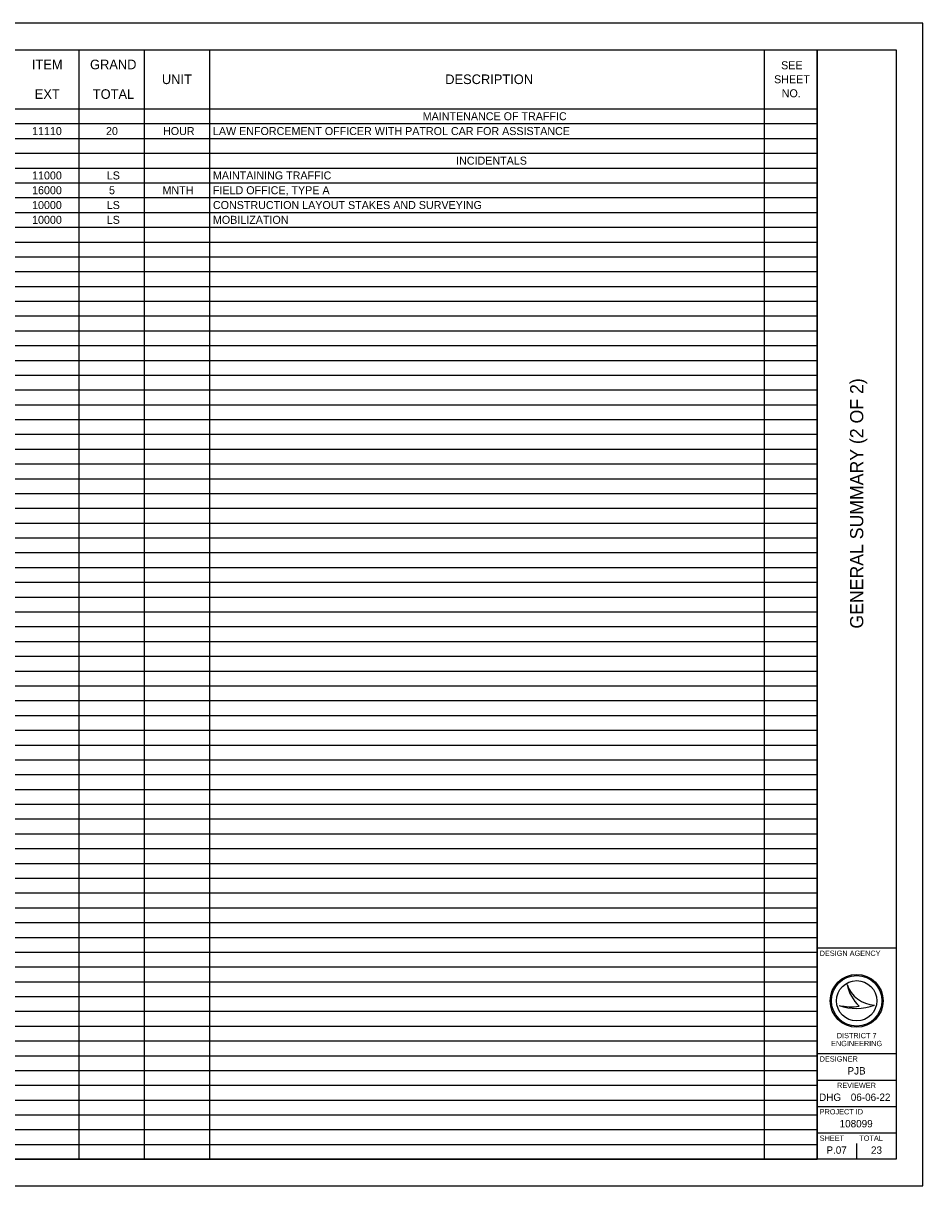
# Model space of a CAD drawing. Extents: x 0 to 34, y 0 to 22.
# Drawn here: x 16.98 to 34, y 0 to 22 of the extents above; entities that cross this region are included whole.
import ezdxf

# ---------------------------------------------------------------- set-up
doc = ezdxf.new("R2010")
doc.units = 0
for name, color, linetype in [('Default', 7, 'Continuous'), ('SH_Border', 7, 'Continuous'), ('SH_Cut_Line', 7, 'Continuous'), ('SH_Data', 7, 'Continuous'), ('SH_Text', 7, 'Continuous')]:
    doc.layers.add(name, color=color, linetype=linetype)

msp = doc.modelspace()

# ---------------------------------------------------------------- linework, layer by layer
at = {"layer": 'Default'}
for p, q in [((1.5, 21.5), (32.001, 21.5)), ((18.035, 21.5), (18.035, 0.502)), ((19.27, 21.5), (19.27, 0.502)), ((20.506, 21.5), (20.506, 0.502)), ((30.997, 21.5), (30.997, 0.502)), ((32.001, 21.5), (32.001, 0.502)), ((1.5, 20.38), (32.001, 20.38)), ((1.5, 20.1), (32.001, 20.1)), ((1.5, 19.82), (32.001, 19.82)), ((1.5, 19.54), (32.001, 19.54)), ((1.5, 19.26), (32.001, 19.26)), ((1.5, 18.98), (32.001, 18.98)), ((1.5, 18.7), (32.001, 18.7)), ((1.5, 18.42), (32.001, 18.42)), ((1.5, 18.14), (32.001, 18.14)), ((1.5, 17.86), (32.001, 17.86)), ((1.5, 17.58), (32.001, 17.58)), ((1.5, 17.3), (32.001, 17.3)), ((1.5, 17.02), (32.001, 17.02)), ((1.5, 16.74), (32.001, 16.74)), ((1.5, 16.46), (32.001, 16.46)), ((1.5, 16.18), (32.001, 16.18)), ((1.5, 15.9), (32.001, 15.9)), ((1.5, 15.62), (32.001, 15.62)), ((1.5, 15.34), (32.001, 15.34)), ((1.5, 15.061), (32.001, 15.061)), ((1.5, 14.781), (32.001, 14.781)), ((1.5, 14.501), (32.001, 14.501)), ((1.5, 14.221), (32.001, 14.221)), ((1.5, 13.941), (32.001, 13.941)), ((1.5, 13.661), (32.001, 13.661)), ((1.5, 13.381), (32.001, 13.381)), ((1.5, 13.101), (32.001, 13.101)), ((1.5, 12.821), (32.001, 12.821)), ((1.5, 12.541), (32.001, 12.541)), ((1.5, 12.261), (32.001, 12.261)), ((1.5, 11.981), (32.001, 11.981)), ((1.5, 11.701), (32.001, 11.701)), ((1.5, 11.421), (32.001, 11.421)), ((1.5, 11.141), (32.001, 11.141)), ((1.5, 10.861), (32.001, 10.861)), ((1.5, 10.581), (32.001, 10.581)), ((1.5, 10.301), (32.001, 10.301)), ((1.5, 10.021), (32.001, 10.021)), ((1.5, 9.741), (32.001, 9.741)), ((1.5, 9.461), (32.001, 9.461)), ((1.5, 9.181), (32.001, 9.181)), ((1.5, 8.901), (32.001, 8.901)), ((1.5, 8.621), (32.001, 8.621)), ((1.5, 8.341), (32.001, 8.341)), ((1.5, 8.061), (32.001, 8.061)), ((1.5, 7.781), (32.001, 7.781)), ((1.5, 7.501), (32.001, 7.501)), ((1.5, 7.221), (32.001, 7.221)), ((1.5, 6.941), (32.001, 6.941)), ((1.5, 6.661), (32.001, 6.661)), ((1.5, 6.381), (32.001, 6.381)), ((1.5, 6.101), (32.001, 6.101)), ((1.5, 5.821), (32.001, 5.821)), ((1.5, 5.541), (32.001, 5.541)), ((1.5, 5.261), (32.001, 5.261)), ((1.5, 4.981), (32.001, 4.981)), ((1.5, 4.701), (32.001, 4.701)), ((1.5, 4.421), (32.001, 4.421)), ((1.5, 4.141), (32.001, 4.141)), ((1.5, 3.861), (32.001, 3.861)), ((1.5, 3.581), (32.001, 3.581)), ((1.5, 3.301), (32.001, 3.301)), ((1.5, 3.021), (32.001, 3.021)), ((1.5, 2.741), (32.001, 2.741)), ((1.5, 2.461), (32.001, 2.461)), ((1.5, 2.182), (32.001, 2.182)), ((1.5, 1.902), (32.001, 1.902)), ((1.5, 1.622), (32.001, 1.622)), ((1.5, 1.342), (32.001, 1.342)), ((1.5, 1.062), (32.001, 1.062)), ((1.5, 0.782), (32.001, 0.782)), ((1.5, 0.502), (32.001, 0.502))]:
    msp.add_line(p, q, dxfattribs=at)
at = {"layer": 'SH_Border'}
for p, q in [((32, 0.5), (32, 21.5)), ((32, 4.5), (33.5, 4.5)), ((32, 2.5), (33.5, 2.5)), ((32, 2), (33.5, 2)), ((32, 1.5), (33.5, 1.5)), ((32, 1), (33.5, 1))]:
    msp.add_line(p, q, dxfattribs=at)
msp.add_lwpolyline([(1.5, 21.5), (33.5, 21.5), (33.5, 0.5), (1.5, 0.5)], close=True, dxfattribs=at)
at = {"layer": 'SH_Cut_Line'}
msp.add_lwpolyline([(0, 0), (34, 0), (34, 22), (0, 22)], close=True, dxfattribs=at)
at = {"layer": 'SH_Data'}
for p, q in [((32.567, 3.81), (32.567, 3.81)), ((32.567, 3.81), (32.567, 3.81)), ((32.417, 3.41), (32.417, 3.41)), ((32.417, 3.41), (32.417, 3.41)), ((32.75, 3.5), (32.75, 3.5)), ((33.087, 3.419), (33.087, 3.419)), ((33.087, 3.419), (33.087, 3.419)), ((32.375, 0.675), (32.375, 0.675)), ((32.75, 0.5), (32.75, 0.8))]:
    msp.add_line(p, q, dxfattribs=at)
for radius in [0.5, 0.5, 0.477, 0.477, 0.477, 0.477, 0.382, 0.382]:
    msp.add_circle((32.75, 3.5), radius, dxfattribs=at)
for centre, radius, start, end in [((33.116, 3.998), 0.58, 198.9257, 198.9319), ((33.347, 3.97), 0.796, 191.6379, 191.6421), ((33.116, 3.998), 0.58, 198.9319, 267.1657), ((33.347, 3.97), 0.796, 191.6421, 226.0947), ((33.116, 3.998), 0.58, 198.9257, 198.9319), ((33.347, 3.97), 0.796, 191.6379, 191.6421), ((33.116, 3.998), 0.58, 198.9319, 267.1657), ((33.347, 3.97), 0.796, 191.6421, 226.0947), ((32.739, 4.37), 1.013, 251.4576, 290.0832), ((32.739, 4.37), 1.013, 251.4576, 290.0832), ((32.648, 4.654), 1.266, 259.4964, 259.4995), ((32.739, 4.37), 1.013, 251.4527, 251.4576), ((32.648, 4.654), 1.266, 259.4964, 259.4995), ((32.739, 4.37), 1.013, 251.4527, 251.4576), ((32.648, 4.654), 1.266, 259.4995, 276.6672), ((32.648, 4.654), 1.266, 259.4995, 276.6672)]:
    msp.add_arc(centre, radius, start, end, dxfattribs=at)

# ---------------------------------------------------------------- texts
at = {"layer": 'Default'}
for s, height, p in [('ITEM', 0.1818, (17.146, 21.129)), ('GRAND', 0.1818, (18.246, 21.129)), ('SEE ', 0.1515, (31.321, 21.129)), ('UNIT', 0.1818, (19.605, 20.849)), ('DESCRIPTION', 0.18182, (24.966, 20.849)), ('SHEET ', 0.1515, (31.188, 20.864)), ('EXT', 0.1818, (17.2, 20.569)), ('TOTAL', 0.1818, (18.298, 20.569)), ('NO.', 0.1515, (31.332, 20.599)), ('MAINTENANCE OF TRAFFIC', 0.15152, (24.54, 20.164)), ('11110', 0.1515, (17.149, 19.884)), ('20', 0.1515, (18.548, 19.884)), ('HOUR', 0.1515, (19.627, 19.884)), ('LAW ENFORCEMENT OFFICER WITH PATROL CAR FOR ASSISTANCE', 0.15152, (20.571, 19.884)), ('INCIDENTALS', 0.15152, (25.172, 19.324)), ('11000', 0.1515, (17.149, 19.044)), ('LS', 0.1515, (18.562, 19.044)), ('MAINTAINING TRAFFIC', 0.15152, (20.571, 19.044)), ('16000', 0.1515, (17.149, 18.764)), ('5', 0.152, (18.605, 18.764)), ('MNTH', 0.1515, (19.616, 18.764)), ('FIELD OFFICE, TYPE A', 0.15152, (20.571, 18.764)), ('10000', 0.1515, (17.149, 18.484)), ('LS', 0.1515, (18.562, 18.484)), ('CONSTRUCTION LAYOUT STAKES AND SURVEYING', 0.15152, (20.571, 18.484)), ('10000', 0.1515, (17.149, 18.204)), ('LS', 0.1515, (18.562, 18.204)), ('MOBILIZATION', 0.15152, (20.571, 18.204))]:
    msp.add_text(s, height=height, dxfattribs=at).set_placement(p)
at = {"layer": 'SH_Data'}
msp.add_text('GENERAL SUMMARY (2 OF 2)', height=0.25, rotation=90, dxfattribs=at).set_placement((32.875, 10.544))
for s, height, p in [('DESIGN AGENCY', 0.1, (32.05, 4.35)), ('DESIGNER', 0.1, (32.05, 2.35)), ('PJB', 0.14, (32.576, 2.105)), ('REVIEWER', 0.1, (32.378, 1.85)), ('DHG', 0.14, (32.039, 1.605)), ('06-06-22', 0.14, (32.639, 1.605)), ('PROJECT ID', 0.1, (32.05, 1.35)), ('108099', 0.14, (32.428, 1.105)), ('SHEET', 0.1, (32.05, 0.85)), ('TOTAL', 0.1, (32.8, 0.85)), ('P.07', 0.14, (32.178, 0.605)), ('23', 0.14, (33.021, 0.605))]:
    msp.add_text(s, height=height, dxfattribs=at).set_placement(p)
at = {"layer": 'SH_Text'}
for s, p in [('DISTRICT 7', (32.374, 2.792)), ('ENGINEERING', (32.265, 2.642))]:
    msp.add_text(s, height=0.1, dxfattribs=at).set_placement(p)

doc.saveas('drawing.dxf')
